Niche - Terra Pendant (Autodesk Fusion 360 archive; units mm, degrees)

design "Terra" references "Niche - Chief Architect - Luxe Single Pendant Cordset", "Terra", "Luxe Single Pendant Cordset - 4ft Standard"
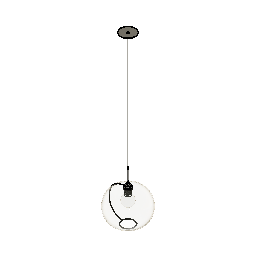
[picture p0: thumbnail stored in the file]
external_derived "ExternalDerived1" bodies "Terra"
external_derived "ExternalDerived2" bodies "Socket Body", "Shade Ring", "Shade Ring +Collar", "Socket", "Body1", "Metal Strain Relief", "Fabric Cord (1)", "Stem (Threaded)"
align "Align1"
external_derived "ExternalDerived3" bodies "G30-Bulb"
align "Align2"
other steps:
derived_base_feature "Derived Base Feature1" bodies "Terra"
derived_base_feature "Derived Base Feature2" bodies "Socket Body", "Shade Ring", "Shade Ring +Collar", "Socket", "Body1", "Metal Strain Relief", "Fabric Cord (1)", "Stem (Threaded)"
derived_base_feature "Derived Base Feature3" bodies "G30-Bulb"
named bodies: "Terra", "Socket Body", "Shade Ring", "Shade Ring +Collar", "Socket", "Body1", "Metal Strain Relief", "Fabric Cord (1)", "Stem (Threaded)", "Cap (Threaded)", "5M Set Screw", "G30-Bulb"

design "Luxe Single Pendant Cordset - 4ft Standard" references "Luxe Canopy - Single Pendant Cordset"
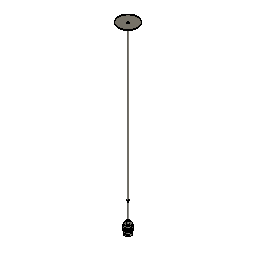
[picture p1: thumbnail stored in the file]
external_derived "ExternalDerived2" bodies "Cap (Threaded)"
move "Move1"
move "Move2"
offset_faces "OffsetFaces1" distance 1051.56
move "Move3"
move "Move4"
move "Move5"
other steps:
derived_base_feature "Derived Base Feature9" bodies "Socket Body", "Shade Ring", "Shade Ring +Collar", "Socket"
derived_base_feature "Derived Base Feature10" bodies "Body1"
derived_base_feature "Derived Base Feature12" bodies "Metal Strain Relief"
derived_base_feature "Derived Base Feature13" bodies "Fabric Cord (1)"
derived_base_feature "Derived Base Feature14" bodies "Stem (Threaded)"
derived_base_feature "Derived Base Feature15" bodies "Cap 9Threaded)", "Cap (Threaded)"
named bodies: "Socket Body", "Shade Ring", "Shade Ring +Collar", "Socket", "Metal Strain Relief", "Fabric Cord (1)", "Stem (Threaded)", "Cap 9Threaded)", "Body1", "Cap (Threaded)", "5M Set Screw"

design "Luxe Canopy - Single Pendant Cordset" references "M5 Set Screw", "Canopy Mounting Bar", "Plastic Strain Relief", "Canopy Mounting Bar Screw", "Luxe Cordset"
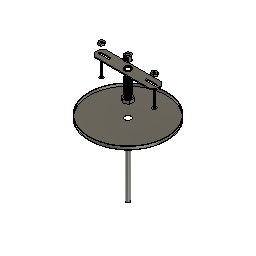
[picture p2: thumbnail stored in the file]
sketch "Sketch1" plane through (0, 0, 0) normal (0, 0, 1) x axis (1, 0, 0)
  circle C1 centre (0, 0) radius 63.5
  point P1 (0, 0)
  point P2 (0, 0)
  coincident P1 P2
  dimension "d1" diameter C1 = 127
extrude "Extrude1" new body sketch "Sketch1" along normal blind 5.08
shell "Shell1" innerThickness 0.762
hole "Hole1" HoleDepth 35.56 HoleDiameter 10.16 TipAngle 118
component_from_bodies "Body->Comp1"
component_insert "Component Insert1"
component_insert "Component Insert2"
component_insert "Component Insert3"
sketch "Sketch2" plane through (0, 0, 0) normal (0, 0, 1) x axis (1, 0, 0)
  circle C1 centre (0, 0) radius 3.175
  point P1 (0, 0)
  point P2 (0, 0)
  coincident P1 P2
  dimension "d8" diameter C1 = 6.35
extrude "Extrude2" new body sketch "Sketch2" along normal blind 127 and against normal blind 127 bodies "Fabric Cord"
component_insert "Component Insert4"
component_insert "Component Insert5"
position "Position1"
sketch "Sketch3" plane through (0, 0, 0.762) normal (0, 0, 1) x axis (-1, 0, 0)
  circle C1 centre (-0.0475, 0.2257) radius 5.08
  circle C2 centre (0, 0) radius 62.738
  circle C3 centre (0, 0) radius 4.826
  concentric C2 C3
  dimension "d13" diameter C3 = 9.652
extrude "Extrude3" new body sketch "Sketch3" profile of C3 along normal blind 25.4 bodies "Threaded Nipple"
shell "Shell2" innerThickness 1.27
thread "Thread1"
sketch "Sketch5" plane through (0, 0, 127) normal (0, 0, 1) x axis (-1, 0, 0)
  line L1 (-6.8191, 3.937) -> (0, 7.874)
  line L2 (-6.8191, -3.937) -> (-6.8191, 3.937)
  line L3 (0, -7.874) -> (-6.8191, -3.937)
  line L4 (6.8191, -3.937) -> (0, -7.874)
  line L5 (6.8191, 3.937) -> (6.8191, -3.937)
  line L6 (0, 7.874) -> (6.8191, 3.937)
  circle C1 centre (0, 0) radius 3.175
  point P2 (0, 0)
  point P9 (0, 0)
  point P3 (0, 7.874)
  coincident P2 P9
  dimension "d20" distance P3 P9 = 7.874
extrude "Extrude4" new body sketch "Sketch5" along normal blind 5.08 bodies "Hex Nut"
move "Move1"
thread "Thread2"
move "Move2" TranslateX 0 TranslateY 0 TranslateZ -55.88
move "Move3" TranslateX 0 TranslateY 0 TranslateZ 60.96
position "Position2"
sketch "Sketch6" plane through (0, 0, 0) normal (0, 0, 1) x axis (1, 0, 0)
  circle C1 centre (0, 0) radius 9.525
  point P1 (0, 0)
  point P2 (0, 0)
  coincident P1 P2
  dimension "d29" diameter C1 = 19.05
extrude "Extrude5" new body sketch "Sketch6" along normal blind 16.129 bodies "Metal Strain Relief"
move "Move4" TranslateX 0 TranslateY 0 TranslateZ -86.36
hole "Hole2" HoleDepth 10.16 HoleDiameter 5.08 TipAngle 118
hole "Hole3" HoleDepth 4.064 HoleDiameter 7.62 TipAngle 180
hole "Hole4" HoleDepth 12.192 HoleDiameter 9.144 TipAngle 180
thread "Thread3" ThreadOffset 0 ThreadLength 6.096
move "Move1" TranslateX 0 TranslateY 0 TranslateZ 68.58
move "Move5" TranslateX 0 TranslateY 0 TranslateZ 138.43
component_insert "Component Insert6"
external_derived "ExternalDerived1" bodies "5M Set Screw"
move "Move6" TranslateX 0 TranslateY 0 TranslateZ -185.42
copy_paste_bodies "CopyPasteBodies1"
move "Move7" TranslateX 0 TranslateY 0 TranslateZ -12.7
offset_faces "OffsetFaces1" distance -152.4
move "Move8"
component_from_bodies "Body->Comp2"
component_from_bodies "Body->Comp3"
component_from_bodies "Body->Comp4"
component_from_bodies "Body->Comp5"
hole "Hole1" HoleDepth 25.4 HoleDiameter 6.35 TipAngle 180
sketch "Sketch7" plane through (0, 0, 0) normal (0, 0, 1) x axis (1, 0, 0)
  line L1 (49.784, 3.9595) -> (52.07, 0)
  line L2 (45.212, 3.9595) -> (49.784, 3.9595)
  line L3 (42.926, 0) -> (45.212, 3.9595)
  line L4 (45.212, -3.9595) -> (42.926, 0)
  line L5 (49.784, -3.9595) -> (45.212, -3.9595)
  line L6 (52.07, 0) -> (49.784, -3.9595)
  point P2 (52.07, 0)
  point P8 (47.498, 0)
  dimension "d63" distance P2 P8 = 4.572
extrude "Extrude6" new body sketch "Sketch7" along normal blind 3.175 bodies "Mounting Hex Nut"
hole "Hole5" HoleDepth 25.4 HoleDiameter 3.81 TipAngle 180
thread "Thread4"
move "Move9"
component_from_bodies "Body->Comp6"
copy_paste "CopyPaste1"
move "Move10"
derived_base_feature "Derived Base Feature3" bodies "Stem (Threaded)", "Cap 9Threaded)"
move "Move11"
component_from_bodies "Body->Comp7"
component_from_bodies "Body->Comp8"
component_from_bodies "Body->Comp9"
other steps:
base_feature "Base Feature1"
base_feature "Base Feature1" bodies "Stem (Threaded)"
base_feature "Base Feature1" bodies "Cap 9Threaded)"
base_feature "Base Feature1" bodies "Fabric Cord"
base_feature "Base Feature1" bodies "Metal Strain Relief"
base_feature "Base Feature1" bodies "Mounting Hex Nut"
base_feature "Base Feature1" bodies "Hex Nut"
base_feature "Base Feature1" bodies "Fabric Cord (1)"
base_feature "Base Feature1" bodies "Threaded Nipple"
derived_base_feature "Derived Base Feature1" bodies "Socket Body", "Shade Ring", "Shade Ring +Collar", "Socket", "Rigid Stem"
derived_base_feature "Derived Base Feature2" bodies "5M Set Screw"
base_feature "Base Feature1" bodies "Fabric Cord", "Fabric Cord (1)"
create_component "CreateComponent1"
remove_body "RemoveBody1"
create_component "CreateComponent2"
remove_body "RemoveBody2"
create_component "CreateComponent3"
remove_body "RemoveBody3"
create_component "CreateComponent4"
remove_body "RemoveBody4"
create_component "CreateComponent5"
remove_body "RemoveBody5"
create_component "CreateComponent6"
remove_body "RemoveBody6"
create_component "CreateComponent7"
remove_body "RemoveBody7"
create_component "CreateComponent8"
remove_body "RemoveBody8"
create_component "CreateComponent9"
remove_body "RemoveBody9"
named bodies: "Fabric Cord", "Threaded Nipple", "Hex Nut", "Metal Strain Relief", "Socket Body", "Shade Ring", "Shade Ring +Collar", "Socket", "Rigid Stem", "5M Set Screw", "Fabric Cord (1)", "Mounting Hex Nut", "Stem (Threaded)", "Cap 9Threaded)"

design "M5 Set Screw"
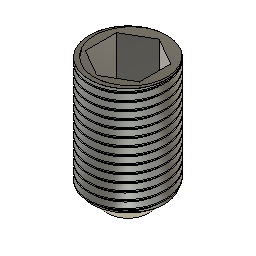
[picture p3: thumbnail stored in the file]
sketch "Sketch1" plane through (0, 0, 0) normal (0, 0, 1) x axis (1, 0, 0)
  circle C1 centre (0, 0) radius 2.5
  point P1 (0, 0)
  point P2 (0, 0)
  coincident P1 P2
  dimension "d1" diameter C1 = 5
extrude "Extrude1" new body sketch "Sketch1" along normal blind 8
sketch "Sketch2" plane through (0, 0, 8) normal (0, 0, 1) x axis (-1, 0, 0)
  line L1 (-1.7321, 1) -> (0, 2)
  line L2 (-1.7321, -1) -> (-1.7321, 1)
  line L3 (0, -2) -> (-1.7321, -1)
  line L4 (1.7321, -1) -> (0, -2)
  line L5 (1.7321, 1) -> (1.7321, -1)
  line L6 (0, 2) -> (1.7321, 1)
  circle C1 centre (0, 0) radius 2.5
  point P2 (0, 0)
  point P9 (0, 0)
  coincident P2 P9
extrude "Extrude2" cut sketch "Sketch2" profile of L1 L2 L3 L4 L5 L6 against normal blind 3
thread "Thread1" ThreadOffset 0.99 ThreadLength 7
chamfer "Chamfer1" distance 1.15

design "Luxe Cordset" references "M5 Set Screw"
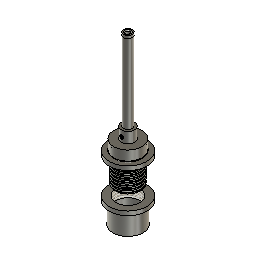
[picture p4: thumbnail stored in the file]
sketch "Sketch1" plane through (0, 0, 0) normal (0, 0, 1) x axis (1, 0, 0)
  circle C1 centre (0, 0) radius 20.6
  point P1 (0, 0)
  point P2 (0, 0)
  coincident P1 P2
  dimension "d11" diameter C1 = 41.2
extrude "Extrude1" new body sketch "Sketch1" along normal blind 14 bodies "Socket Body"
sketch "Sketch2" plane through (0, 0, 14) normal (0, 0, 1) x axis (-1, 0, 0)
  circle C1 centre (0, 0) radius 20.6
  circle C2 centre (0, 0) radius 9.6
  concentric C1 C2
  dimension "d3" diameter C2 = 19.2
extrude "Extrude2" add sketch "Sketch2" profile of C2 along normal blind 15.75
sketch "Sketch3" plane through (0, 0, 29.75) normal (0, 0, 1) x axis (-1, 0, 0)
  circle C1 centre (0, 0) radius 9.6
  circle C2 centre (0, 0) radius 5.75
  concentric C1 C2
  dimension "d6" diameter C2 = 11.5
extrude "Extrude3" new body sketch "Sketch3" profile of C2 along normal blind 114 bodies "Rigid Stem"
move "Move1"
sketch "Sketch4" plane through (0, 0, 203.75) normal (0, 0, 1) x axis (-1, 0, 0)
  circle C1 centre (0, 0) radius 5.75
  circle C2 centre (0, 0) radius 27.5
  dimension "d10" diameter C2 = 55
extrude "Extrude4" new body sketch "Sketch4" profile of C2 along normal blind 6 bodies "Shade Ring"
hole "Hole1" HoleDepth 25 HoleDiameter 42.75 TipAngle 118
sketch "Sketch5" plane through (0, 0, 0) normal (0, 0, 1) x axis (1, 0, 0)
  circle C1 centre (0, 0) radius 22
  point P1 (0, 0)
  point P2 (0, 0)
  coincident P1 P2
  dimension "d18" diameter C1 = 44
move "Move2"
copy_paste_bodies "CopyPasteBodies1"
move "Move3"
sketch "Sketch6" plane through (0, 0, 60) normal (0, 0, -1) x axis (1, 0, 0)
  circle C1 centre (0, 0) radius 20.6
  circle C2 centre (0, 0) radius 21.375
  circle C3 centre (0, 0) radius 20
  concentric C1 C2
  concentric C1 C3
  dimension "d21" diameter C2 = 42.75
  dimension "d24" diameter C3 = 40
cylinder_primitive "CylinderPrimitive1" Height 8 Diameter 42.75
thread "Thread1"
thread "Thread3"
hole "Hole2" HoleDepth 18 HoleDiameter 39 TipAngle 180
move "Move4"
move "Move5"
move "Move6"
hole "Hole3" HoleDepth 114 HoleDiameter 7.6 TipAngle 180
derived_base_feature "Derived Base Feature" bodies "Socket"
move "Move7"
scale "Scale1" ScaleX 1.2 ScaleY 1.2
move "Move8"
sketch "Sketch8" plane through (0, 0, -23.9827) normal (0, 0, -1) x axis (1, 0, 0)
  circle C1 centre (0, -0.036) radius 27.5
  circle C2 centre (0, -0.036) radius 22
  circle C3 centre (0, -0.036) radius 19.5
  dimension "d36" diameter C2 = 44
  dimension "d42" = -2.5
extrude "Extrude7" add sketch "Sketch8" profile of C2 C3 along normal blind 30
offset_faces "OffsetFaces1" distance 2.75
offset_faces "OffsetFaces2" distance -9
thread "Thread2"
move "Move9"
move "Move10"
move "Move11"
scale "Scale2" ScaleZ 1.2
move "Move12"
move "Move13"
move "Move14"
move "Move15"
move "Move16"
split_face "SplitFace1"
move "Move17"
move "Move18"
move "Move19"
move "Move20"
move "Move21"
move "Move22"
move "Move23"
move "Move24"
move "Move25"
move "Move26"
move "Move27"
thread "Thread4"
move "Move28"
move "Move29"
move "Move30"
hole "Hole4" HoleDepth 21 HoleDiameter 39.35 TipAngle 180
hole "Hole5" HoleDepth 9 HoleDiameter 5 TipAngle 180
move "Move31"
move "Move32"
hole "Hole6" HoleDepth 20 HoleDiameter 10 TipAngle 180
move_face "MoveFace3"
move "Move33"
move "Move34"
move "Move35"
move "Move36"
move "Move37"
thread "Thread5" ThreadOffset 0 ThreadLength 6
thread "Thread6" ThreadOffset 0 ThreadLength 6
move "Move38"
move "Move39"
move "Move40"
move "Move41"
component_insert "Component Insert"
thread "Thread7" ThreadOffset 0.5 ThreadLength 5.337
chamfer "Chamfer1" distance 0.5 distance 0.35
sketch "Sketch12" plane through (0, 0, 0) normal (0, 0, 1) x axis (1, 0, 0)
  circle C1 centre (0, 0) radius 6.35
  dimension "d60" diameter C1 = 12.7
extrude "Extrude8" new body sketch "Sketch12" along normal blind 115 bodies "Stem (Threaded)"
hole "Hole7" HoleDepth 115 HoleDiameter 9.65 TipAngle 118
thread "Thread8" ThreadOffset 0 ThreadLength 12.5
thread "Thread9" ThreadOffset 0 ThreadLength 12.5
sketch "Sketch13" plane through (0, 0, 0) normal (0, 0, 1) x axis (1, 0, 0)
  circle C1 centre (0, 0) radius 6.35
  point P1 (0, 0)
  point P2 (0, 0)
  coincident P1 P2
  dimension "d70" diameter C1 = 12.7
extrude "Extrude9" new body sketch "Sketch13" along normal blind 4 bodies "Cap 9Threaded)"
sketch "Sketch14" plane through (0, 0, 4) normal (0, 0, 1) x axis (-1, 0, 0)
  circle C1 centre (0, 0) radius 6.35
  circle C2 centre (0, 0) radius 4.5
  concentric C1 C2
  dimension "d73" diameter C2 = 9
extrude "Extrude10" add sketch "Sketch14" profile of C2 against normal blind 14
thread "Thread10"
hole "Hole8" HoleDepth 115 HoleDiameter 6.5 TipAngle 118 CSDiameter 9 CSAngle 90
move "Move42"
move "Move43"
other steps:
base_feature "Base Feature" bodies "Shade Ring +Collar"
named bodies: "Socket Body", "Shade Ring", "Shade Ring +Collar", "Socket", "Rigid Stem", "Stem (Threaded)", "Cap 9Threaded)"

design "Niche - Chief Architect - Luxe Single Pendant Cordset"
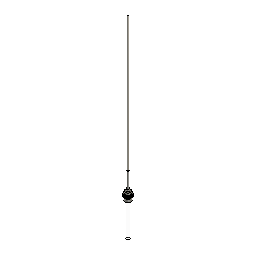
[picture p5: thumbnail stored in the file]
derived_base_feature "Derived Base Feature" bodies "Socket Body", "Shade Ring", "Shade Ring +Collar", "Socket", "Canopy", "Metal Strain Relief", "Fabric Cord (1)", "Stem (Threaded)"
remove_body "RemoveBody1"
remove_body "RemoveBody2"
split "Split1" bodies "Socket Body (1)"
remove_body "RemoveBody3"
align "Align1"
hole "Hole1" HoleDepth 19.05 HoleDiameter 8.89 TipAngle 118
combine "Combine1" bodies "Shade Ring"
split "Split2" bodies "Socket (1)"
remove_body "RemoveBody4"
split "Split3" bodies "Fabric Cord (1) (1)"
remove_body "RemoveBody5"
combine "Combine2" bodies "Socket Body"
align "Align2"
combine "Combine3" bodies "Metal Strain Relief"
sketch "Sketch1" plane through (0, 0, 0) normal (0, 1, 0) x axis (1, 0, 0)
  line L1 (13.1098, 24.9049) -> (-12.2902, 24.9049)
  line L2 (18.1898, 37.1766) -> (18.1898, 29.9849)
  line L3 (-17.3702, 29.9849) -> (-17.3702, 36.7132)
  line L4 (0, 132.969) -> (0, 24.9049)
  arc A1 centre (0, 86.36) radius 46.609 clockwise from (-22.6031, 45.5985) to (23.276, 45.979)
  arc A2 centre (-27.5302, 36.7132) radius 10.16 clockwise from (-22.6031, 45.5985) to (-17.3702, 36.7132)
  arc A3 centre (28.3498, 37.1766) radius 10.16 clockwise from (18.1898, 37.1766) to (23.276, 45.979)
  arc A4 centre (-12.2902, 29.9849) radius 5.08 clockwise from (-12.2902, 24.9049) to (-17.3702, 29.9849)
  arc A5 centre (13.1098, 29.9849) radius 5.08 clockwise from (18.1898, 29.9849) to (13.1098, 24.9049)
  point P5 (18.1898, 43.4469)
  point P3 (-17.3702, 24.9049)
  point P4 (18.1898, 24.9049)
  point P18 (0, 24.9049)
  point P19 (0, 132.969)
  horizontal L1
  vertical L2
  vertical L3
  tangent A1 A2
  tangent L3 A2
  coincident P5 L2
  coincident P5 A1
  tangent L2 A3
  tangent A1 A3
  equal A2 A3
  coincident P3 L1
  coincident P3 L3
  tangent L1 A4
  tangent L3 A4
  coincident P4 L1
  coincident P4 L2
  tangent L1 A5
  tangent L2 A5
  coincident L1 P18
  coincident A1 P19
  perpendicular L1 L4
  dimension "d4" diameter A1 = 93.218
  dimension "d5" distance P3 P4 = 35.56
  dimension "d6" distance P4 P5 = 18.542
  dimension "d7" radius A2 = 10.16
  dimension "d8" radius A4 = 5.08
  dimension "d9" radius A5 = 5.08
revolve "Revolve1" sketch "Sketch1" AlongAngle 360 bodies "G30-Bulb"
move "Move1"
sketch "Sketch2" plane through (0, 0, 0) normal (0, 1, 0) x axis (1, 0, 0)
  line L1 (12.7, 0) -> (-12.7, 0)
  line L2 (12.7, 152.4) -> (12.7, 0)
  line L3 (-12.7, 0) -> (-12.7, 152.4)
  line L4 (0, 165.1) -> (0, 0)
  arc A1 centre (0, 152.4) radius 12.7 clockwise from (-12.7, 152.4) to (12.7, 152.4)
  point P1 (0, 0)
  point P7 (0, 0)
  point P8 (0, 165.1)
  horizontal L1
  vertical L2
  vertical L3
  coincident P1 P7
  midpoint A1 P8
  perpendicular L1 L4
revolve "Revolve2" sketch "Sketch2" AlongAngle 360 bodies "T9-Bulb"
move "Move2"
sketch "Sketch3" plane through (0, 0, 0) normal (0, 1, 0) x axis (1, 0, 0)
  line L1 (12.7, 0) -> (-12.7, 0)
  line L2 (12.7, 254) -> (12.7, 0)
  line L3 (-12.7, 0) -> (-12.7, 254)
  line L4 (0, 266.7) -> (0, 0)
  arc A1 centre (0, 254) radius 12.7 clockwise from (-12.7, 254) to (12.7, 254)
  point P1 (0, 0)
  point P7 (0, 0)
  point P8 (0, 266.7)
  horizontal L1
  vertical L2
  vertical L3
  coincident P1 P7
  midpoint A1 P8
  perpendicular L1 L4
revolve "Revolve3" sketch "Sketch3" AlongAngle 360 bodies "T8-Bulb"
move "Move3"
move "Move4"
move "Move5"
sketch "Sketch4" plane through (0, 0, 0) normal (0, 1, 0) x axis (1, 0, 0)
  line L1 (15.875, -8.763) -> (-15.875, -8.763)
  line L2 (15.875, 22.987) -> (15.875, -8.763)
  line L3 (-15.875, 22.987) -> (15.875, 22.987)
  line L4 (-15.875, -8.763) -> (-15.875, 22.987)
  line L5 (0, 22.987) -> (0, -8.763)
  point P6 (0, -8.763)
  point P7 (0, 22.987)
  point P2 (-15.875, -8.763)
  point P3 (15.875, -8.763)
  point P5 (-15.875, 22.987)
  horizontal L1
  vertical L2
  horizontal L3
  vertical L4
  midpoint L1 P6
  midpoint L3 P7
  dimension "d13" distance P2 P3 = 31.75
  dimension "d14" distance P2 P5 = 31.75
revolve "Revolve4" sketch "Sketch4" AlongAngle 360 bodies "Bulb Extender"
move "Move6"
sketch "Sketch5" plane through (0, 0, 0) normal (0, 1, 0) x axis (1, 0, 0)
  line L1 (-12.7, 35.56) -> (12.7, 35.56)
  line L2 (-12.7, 5.08) -> (-12.7, 35.56)
  line L3 (12.7, 5.08) -> (-12.7, 5.08)
  line L4 (12.7, 35.56) -> (12.7, 5.08)
  line L5 (-12.7, 5.08) -> (12.7, 35.56)
  line L6 (12.7, 5.08) -> (-12.7, 35.56)
  line L7 (0, 35.56) -> (0, 5.08)
  point P6 (0, 20.32)
  point P7 (0, 5.08)
  point P8 (0, 35.56)
  horizontal L1
  perpendicular L1 L2
  parallel L1 L3
  parallel L2 L4
  coincident L5 P6
  coincident L6 P6
  midpoint L3 P7
  midpoint L1 P8
revolve "Revolve5" sketch "Sketch5" AlongAngle 360 bodies "Y-Spliter"
sketch "Sketch6" plane through (0, 0, 0) normal (0, 1, 0) x axis (1, 0, 0)
  line L1 (-55.88, 64.9514) -> (-21.59, 64.9514)
  line L2 (-55.88, 35.7414) -> (-55.88, 64.9514)
  line L3 (-21.59, 35.7414) -> (-55.88, 35.7414)
  line L4 (-21.59, 64.9514) -> (-21.59, 35.7414)
  line L5 (-55.88, 35.7414) -> (-21.59, 64.9514)
  line L6 (-21.59, 35.7414) -> (-55.88, 64.9514)
  line L7 (-38.735, 64.9514) -> (-38.735, 35.7414)
  point P6 (-38.735, 50.3464)
  point P7 (-38.735, 35.7414)
  point P8 (-38.735, 64.9514)
  point P4 (-55.88, 35.7414)
  point P5 (-21.59, 35.7414)
  point P2 (-21.59, 64.9514)
  horizontal L1
  perpendicular L1 L2
  parallel L1 L3
  parallel L2 L4
  coincident L5 P6
  coincident L6 P6
  midpoint L3 P7
  midpoint L1 P8
  dimension "d17" distance P4 P5 = 34.29
  dimension "d18" distance P2 P5 = 29.21
revolve "Revolve6" sketch "Sketch6" AlongAngle 360
chamfer "Chamfer1" distance 7.62
move "Move7"
mirror "Mirror1" mirrorStitchTolerance 0.1016
move "Move8"
combine "Combine4"
move "Move9"
sketch "Sketch7" plane through (0, 0, 0) normal (0, 1, 0) x axis (1, 0, 0)
  line L1 (-15.24, 40.64) -> (-15.24, 48.1816)
  line L2 (12.7, 38.1) -> (-12.7, 38.1)
  line L3 (15.24, 48.1816) -> (15.24, 40.64)
  line L4 (0, 100.1623) -> (0, 38.1)
  arc A1 centre (0, 76.2) radius 23.9623 clockwise from (-19.7282, 62.5988) to (19.7282, 62.5988)
  arc A2 centre (-40.64, 48.1816) radius 25.4 clockwise from (-19.7282, 62.5988) to (-15.24, 48.1816)
  arc A3 centre (40.64, 48.1816) radius 25.4 clockwise from (15.24, 48.1816) to (19.7282, 62.5988)
  arc A4 centre (-12.7, 40.64) radius 2.54 clockwise from (-12.7, 38.1) to (-15.24, 40.64)
  arc A5 centre (12.7, 40.64) radius 2.54 clockwise from (15.24, 40.64) to (12.7, 38.1)
  point P15 (0, 38.1)
  point P16 (0, 100.1623)
  parallel L1 L3
  tangent A1 A2
  tangent L1 A2
  tangent A1 A3
  tangent L3 A3
  tangent L1 A4
  tangent L2 A4
  tangent L2 A5
  tangent L3 A5
  midpoint L2 P15
  midpoint A1 P16
  perpendicular L2 L4
  dimension "d23" radius A2 = 25.4
  dimension "d24" radius A3 = 25.4
  dimension "d25" radius A4 = 2.54
  dimension "d26" radius A5 = 2.54
revolve "Revolve7" sketch "Sketch7" AlongAngle 360 bodies "A15-Bulb"
move "Move10"
copy_paste_bodies "CopyPasteBodies1"
copy_paste_bodies "CopyPasteBodies2"
move "Move11"
mirror "Mirror2" mirrorStitchTolerance 0.1016 bodies "A15-Bulb (1) (1)"
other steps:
base_feature "Base Feature1" bodies "Y-Spliter", "Bulb Extender", "Y-Spliter (1)", "Bulb Extender (1)"
base_feature "Base Feature2" bodies "A15-Bulb", "A15-Bulb (1)"
named bodies: "Socket Body", "Shade Ring", "Shade Ring +Collar", "Socket", "Canopy", "Metal Strain Relief", "Fabric Cord (1)", "Stem (Threaded)", "Adapter", "5M Set Screw", "Body1 (1)", "Socket Body (1)", "Socket (1)", "Fabric Cord (1) (1)", "G30-Bulb", "T9-Bulb", "T8-Bulb", "Bulb Extender", "Y-Spliter", "A15-Bulb", "Y-Spliter (1)", "Bulb Extender (1)", "A15-Bulb (1)", "A15-Bulb (1) (1)"

design "Terra" references "Niche_Terra_Single_Pendant_NURBS"
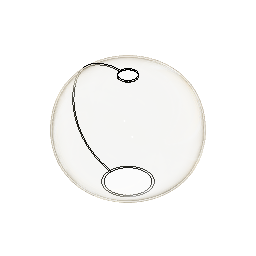
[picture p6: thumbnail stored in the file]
external_derived "ExternalDerived" bodies "Terra"
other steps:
derived_base_feature "Derived Base Feature" bodies "Terra"
named bodies: "Terra"

design "Niche_Terra_Single_Pendant_NURBS"
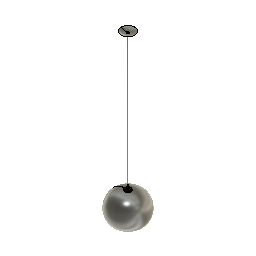
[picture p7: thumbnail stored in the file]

design "Plastic Strain Relief"
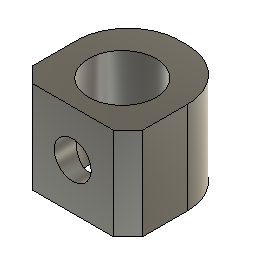
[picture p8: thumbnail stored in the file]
base_feature "Base Feature" bodies "strainrelief"
named bodies: "strainrelief"

design "Canopy Mounting Bar Screw"
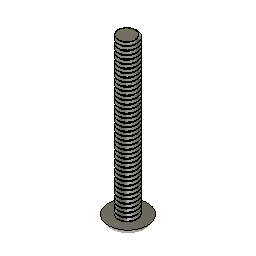
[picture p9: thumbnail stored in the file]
base_feature "Base Feature" bodies "screw1"
named bodies: "screw1"

design "Canopy Mounting Bar"
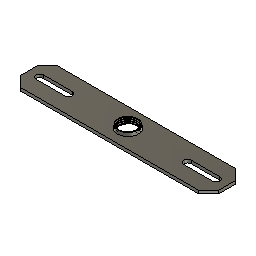
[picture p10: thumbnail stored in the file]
base_feature "Base Feature" bodies "mountingbar"
named bodies: "mountingbar"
